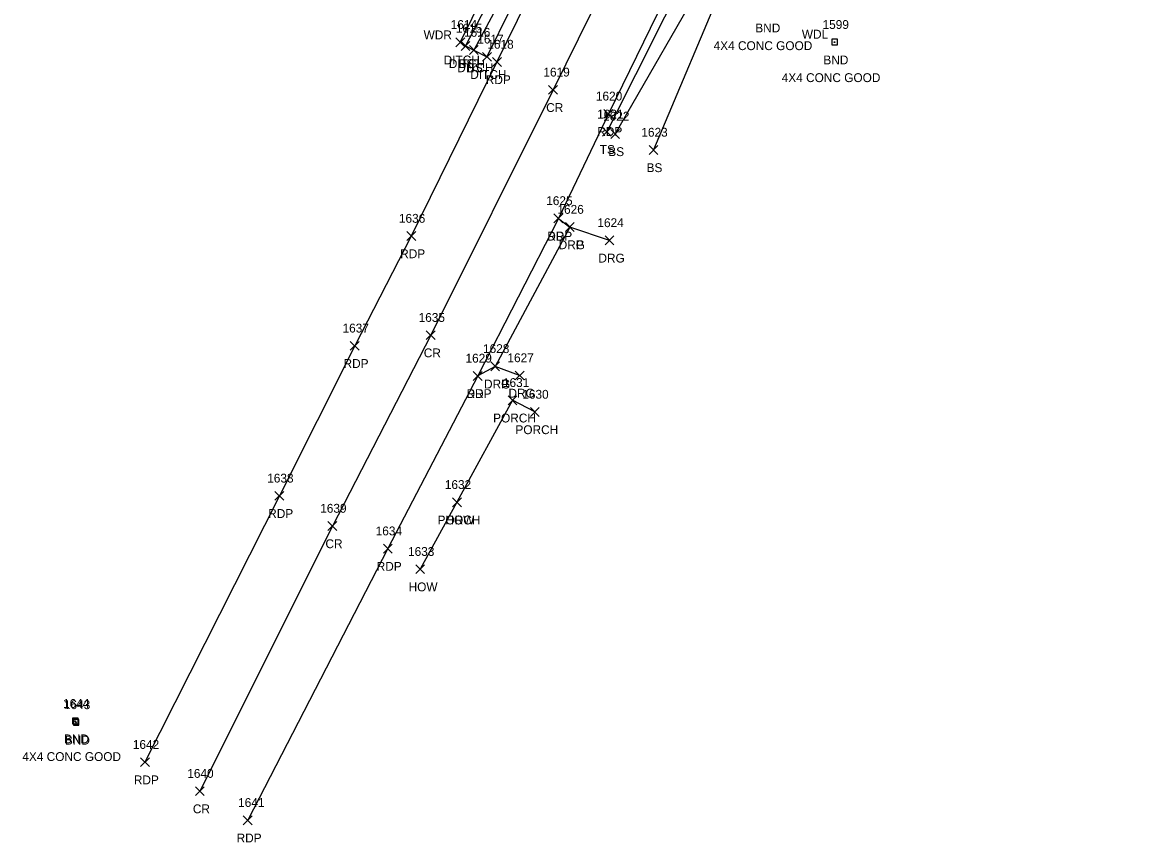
# Model space of a CAD drawing. Extents: x 1551995 to 1555700, y 777276 to 783130.
# Drawn here: x 1554635 to 1554889.9, y 777276.2 to 777461.3 of the extents above; entities that cross this region are included whole.
import ezdxf

# ---------------------------------------------------------------- set-up
doc = ezdxf.new("R2010")
doc.units = 0
for name, color, linetype in [('D_A', 7, 'Continuous'), ('D_I', 7, 'Continuous'), ('D_TIC', 7, 'Continuous'), ('DD', 7, 'Continuous'), ('L_A', 7, 'Continuous'), ('L_I', 7, 'Continuous'), ('L_TIC', 7, 'Continuous'), ('LBC', 7, 'Continuous'), ('LBF', 7, 'Continuous'), ('LELB', 7, 'Continuous'), ('Level 18', 7, 'Continuous'), ('M_A', 7, 'Continuous'), ('M_C', 7, 'Continuous'), ('M_I', 7, 'Continuous'), ('P_A', 7, 'Continuous'), ('P_I', 7, 'Continuous'), ('P_TIC', 7, 'Continuous'), ('PET', 7, 'Continuous'), ('PRC', 7, 'Continuous'), ('R_A', 7, 'Continuous'), ('R_I', 7, 'Continuous'), ('R_TIC', 7, 'Continuous'), ('RDG', 7, 'Continuous'), ('RDP', 7, 'Continuous')]:
    doc.layers.add(name, color=color, linetype=linetype)

msp = doc.modelspace()

# ---------------------------------------------------------------- linework, layer by layer
at = {"layer": 'D_TIC'}
for points in [[(1554732.83, 777455.87), (1554734.83, 777457.87)], [(1554734.83, 777455.87), (1554732.83, 777457.87)], [(1554734, 777455.04), (1554736, 777457.04)], [(1554736, 777455.04), (1554734, 777457.04)], [(1554735.9, 777454.11), (1554737.9, 777456.11)], [(1554737.9, 777454.11), (1554735.9, 777456.11)], [(1554738.85, 777452.59), (1554740.85, 777454.59)], [(1554740.85, 777452.59), (1554738.85, 777454.59)], [(1554738.85, 777452.59), (1554740.85, 777454.59)], [(1554740.85, 777452.59), (1554738.85, 777454.59)]]:
    msp.add_lwpolyline(points, dxfattribs=at)
at = {"layer": 'DD'}
for points in [[(1554853.39, 777826.98), (1554841.81, 777777.5), (1554835.76, 777743.69), (1554828.13, 777697.14), (1554822.33, 777678.76), (1554820.5, 777673.08), (1554821.28, 777667.69), (1554820.54, 777665.87), (1554819.99, 777658.61), (1554821.52, 777659.17), (1554812.27, 777628.19), (1554798.58, 777600.46), (1554777.91, 777552.75), (1554765.73, 777525.09), (1554749.72, 777489.17), (1554733.83, 777456.87), (1554735, 777456.04), (1554736.9, 777455.11), (1554739.85, 777453.59)], [(1554815.91, 777627.5), (1554804.43, 777598.27), (1554784.48, 777549.49), (1554771.86, 777522.02), (1554755.84, 777486.17), (1554739.85, 777453.59)]]:
    msp.add_lwpolyline(points, dxfattribs=at)
at = {"layer": 'L_TIC'}
for points in [[(1554734, 777455.04), (1554736, 777457.04)], [(1554736, 777455.04), (1554734, 777457.04)], [(1554735.9, 777454.11), (1554737.9, 777456.11)], [(1554737.9, 777454.11), (1554735.9, 777456.11)], [(1554765.91, 777435.65), (1554767.91, 777437.65)], [(1554767.91, 777435.65), (1554765.91, 777437.65)], [(1554767.81, 777435.17), (1554769.81, 777437.17)], [(1554769.81, 777435.17), (1554767.81, 777437.17)], [(1554776.45, 777431.55), (1554778.45, 777433.55)], [(1554778.45, 777431.55), (1554776.45, 777433.55)], [(1554744.63, 777375.02), (1554746.63, 777377.02)], [(1554746.63, 777375.02), (1554744.63, 777377.02)], [(1554749.65, 777372.38), (1554751.65, 777374.38)], [(1554751.65, 777372.38), (1554749.65, 777374.38)], [(1554732.08, 777351.99), (1554734.08, 777353.99)], [(1554734.08, 777351.99), (1554732.08, 777353.99)], [(1554732.08, 777351.99), (1554734.08, 777353.99)], [(1554734.08, 777351.99), (1554732.08, 777353.99)], [(1554723.77, 777336.88), (1554725.77, 777338.88)], [(1554725.77, 777336.88), (1554723.77, 777338.88)]]:
    msp.add_lwpolyline(points, dxfattribs=at)
at = {"layer": 'LBC'}
msp.add_lwpolyline([(1554733.08, 777352.99), (1554724.77, 777337.88)], dxfattribs=at)
at = {"layer": 'LBF'}
msp.add_lwpolyline([(1554750.65, 777373.38), (1554745.63, 777376.02), (1554733.08, 777352.99)], dxfattribs=at)
at = {"layer": 'LELB'}
for points in [[(1554855.73, 777827.33), (1554843.83, 777776.52), (1554838.11, 777743.68), (1554829.99, 777696.83), (1554823.99, 777679.3), (1554821.48, 777673.86), (1554821.86, 777673.52), (1554823.73, 777663.64), (1554822.4, 777659.03), (1554813.94, 777627.98), (1554800.18, 777599.92), (1554780.06, 777551.51), (1554767.45, 777524.55), (1554751.73, 777488.16), (1554735, 777456.04)], [(1554857.76, 777827.38), (1554846.36, 777775.83), (1554840.77, 777743.18), (1554831.41, 777696.67), (1554825.48, 777677.69), (1554824.51, 777673.63), (1554823.78, 777673.32), (1554824.92, 777663.42), (1554823.59, 777658.72), (1554814.97, 777627.54), (1554801.99, 777599.47), (1554782.65, 777550.32), (1554769.22, 777523.47), (1554754.18, 777487.46), (1554736.9, 777455.11)], [(1554865.05, 777604.93), (1554861.66, 777583.06), (1554845.3, 777549.29), (1554838.79, 777524.5), (1554825.26, 777531.03), (1554821.87, 777528.28), (1554813.37, 777517.61), (1554805.18, 777504.08), (1554790.4, 777473.73), (1554768.81, 777436.17)], [(1554824.88, 777531.45), (1554822.62, 777533.94), (1554819.85, 777529.46), (1554812.02, 777518.71), (1554803.48, 777505.5), (1554786.44, 777475.49), (1554766.91, 777436.65)], [(1554824.11, 777527.47), (1554814.83, 777516.49), (1554807.91, 777502.52), (1554794.11, 777472.13), (1554777.45, 777432.55)]]:
    msp.add_lwpolyline(points, dxfattribs=at)
at = {"layer": 'Level 18'}
for p, q in [((1554818.99, 777457.54), (1554817.74, 777457.54)), ((1554817.74, 777457.54), (1554817.74, 777456.29)), ((1554818.99, 777457.54), (1554817.74, 777457.54)), ((1554817.74, 777457.54), (1554817.74, 777456.29)), ((1554818.99, 777456.29), (1554818.99, 777457.54)), ((1554818.99, 777456.29), (1554818.99, 777457.54)), ((1554817.74, 777456.29), (1554818.99, 777456.29)), ((1554817.74, 777456.29), (1554818.99, 777456.29)), ((1554647.51, 777304.22), (1554646.26, 777304.22)), ((1554646.26, 777304.22), (1554646.26, 777302.97)), ((1554647.51, 777304.22), (1554646.26, 777304.22)), ((1554646.26, 777304.22), (1554646.26, 777302.97)), ((1554647.71, 777303.93), (1554646.46, 777303.93)), ((1554646.46, 777303.93), (1554646.46, 777302.68)), ((1554647.71, 777303.93), (1554646.46, 777303.93)), ((1554646.46, 777303.93), (1554646.46, 777302.68)), ((1554647.51, 777302.97), (1554647.51, 777304.22)), ((1554647.51, 777302.97), (1554647.51, 777304.22)), ((1554647.71, 777302.68), (1554647.71, 777303.93)), ((1554647.71, 777302.68), (1554647.71, 777303.93)), ((1554646.26, 777302.97), (1554647.51, 777302.97)), ((1554646.26, 777302.97), (1554647.51, 777302.97)), ((1554646.46, 777302.68), (1554647.71, 777302.68)), ((1554646.46, 777302.68), (1554647.71, 777302.68))]:
    msp.add_line(p, q, dxfattribs=at)
for centre in [(1554818.34, 777456.88), (1554646.86, 777303.56), (1554647.06, 777303.27)]:
    msp.add_circle(centre, 0.0833, dxfattribs=at)
at = {"layer": 'P_TIC'}
for points in [[(1554741.1, 777451.42), (1554743.1, 777453.42)], [(1554743.1, 777451.42), (1554741.1, 777453.42)], [(1554753.78, 777445.13), (1554755.78, 777447.13)], [(1554755.78, 777445.13), (1554753.78, 777447.13)], [(1554766.28, 777439.72), (1554768.28, 777441.72)], [(1554768.28, 777439.72), (1554766.28, 777441.72)], [(1554754.97, 777416.1), (1554756.97, 777418.1)], [(1554756.97, 777416.1), (1554754.97, 777418.1)], [(1554721.77, 777412.11), (1554723.77, 777414.11)], [(1554723.77, 777412.11), (1554721.77, 777414.11)], [(1554726.16, 777389.73), (1554728.16, 777391.73)], [(1554728.16, 777389.73), (1554726.16, 777391.73)], [(1554708.98, 777387.33), (1554710.98, 777389.33)], [(1554710.98, 777387.33), (1554708.98, 777389.33)], [(1554736.76, 777380.53), (1554738.76, 777382.53)], [(1554738.76, 777380.53), (1554736.76, 777382.53)], [(1554691.97, 777353.45), (1554693.97, 777355.45)], [(1554693.97, 777353.45), (1554691.97, 777355.45)], [(1554703.95, 777346.63), (1554705.95, 777348.63)], [(1554705.95, 777346.63), (1554703.95, 777348.63)], [(1554716.46, 777341.52), (1554718.46, 777343.52)], [(1554718.46, 777341.52), (1554716.46, 777343.52)], [(1554661.63, 777293.3), (1554663.63, 777295.3)], [(1554663.63, 777293.3), (1554661.63, 777295.3)], [(1554674, 777286.76), (1554676, 777288.76)], [(1554676, 777286.76), (1554674, 777288.76)], [(1554684.83, 777280.18), (1554686.83, 777282.18)], [(1554686.83, 777280.18), (1554684.83, 777282.18)]]:
    msp.add_lwpolyline(points, dxfattribs=at)
at = {"layer": 'PET'}
for points in [[(1554862.74, 777826.66), (1554851.19, 777774.32), (1554844.64, 777742.45), (1554834.58, 777696.01), (1554825.9, 777662.94), (1554824.47, 777658.25), (1554815.91, 777627.5), (1554805.87, 777597.98), (1554786.84, 777548.46), (1554774.55, 777520.74), (1554758.12, 777485.1), (1554742.1, 777452.42), (1554722.77, 777413.11), (1554709.98, 777388.33), (1554692.97, 777354.45), (1554662.63, 777294.3)], [(1554889.9, 777822.39), (1554877.4, 777767.74), (1554869.61, 777731.46), (1554860.02, 777689.61), (1554848.79, 777645.37), (1554834.77, 777600.99), (1554821.88, 777564.77), (1554812, 777537.71), (1554799.6, 777509.17), (1554784.62, 777476.27), (1554767.28, 777440.72), (1554755.97, 777417.1), (1554737.76, 777381.53), (1554717.46, 777342.52), (1554685.83, 777281.18)]]:
    msp.add_lwpolyline(points, dxfattribs=at)
at = {"layer": 'PRC'}
msp.add_lwpolyline([(1554876.72, 777824.26), (1554864.6, 777770.35), (1554858.03, 777739.92), (1554847.21, 777693.38), (1554836.59, 777653.01), (1554828.61, 777623.61), (1554818.04, 777593.07), (1554799.63, 777543.85), (1554787.19, 777515.25), (1554771.79, 777480.71), (1554754.78, 777446.13), (1554727.16, 777390.73), (1554704.95, 777347.63), (1554675, 777287.76)], dxfattribs=at)
at = {"layer": 'R_TIC'}
for points in [[(1554754.97, 777416.1), (1554756.97, 777418.1)], [(1554756.97, 777416.1), (1554754.97, 777418.1)], [(1554757.57, 777414.14), (1554759.57, 777416.14)], [(1554759.57, 777414.14), (1554757.57, 777416.14)], [(1554757.57, 777414.14), (1554759.57, 777416.14)], [(1554759.57, 777414.14), (1554757.57, 777416.14)], [(1554766.53, 777411.13), (1554768.53, 777413.13)], [(1554768.53, 777411.13), (1554766.53, 777413.13)], [(1554740.7, 777382.69), (1554742.7, 777384.69)], [(1554742.7, 777382.69), (1554740.7, 777384.69)], [(1554740.7, 777382.69), (1554742.7, 777384.69)], [(1554742.7, 777382.69), (1554740.7, 777384.69)], [(1554746.22, 777380.63), (1554748.22, 777382.63)], [(1554748.22, 777380.63), (1554746.22, 777382.63)], [(1554736.76, 777380.53), (1554738.76, 777382.53)], [(1554738.76, 777380.53), (1554736.76, 777382.53)]]:
    msp.add_lwpolyline(points, dxfattribs=at)
at = {"layer": 'RDG'}
for points in [[(1554767.53, 777412.13), (1554758.57, 777415.14)], [(1554747.22, 777381.63), (1554741.7, 777383.69)]]:
    msp.add_lwpolyline(points, dxfattribs=at)
at = {"layer": 'RDP'}
msp.add_lwpolyline([(1554755.97, 777417.1), (1554758.57, 777415.14), (1554741.7, 777383.69), (1554737.76, 777381.53)], dxfattribs=at)

# ---------------------------------------------------------------- texts
at = {"layer": 'D_A'}
for p in [(1554730.07, 777451.87), (1554731.24, 777451.04), (1554733.14, 777450.11), (1554736.08, 777448.59), (1554736.08, 777448.59)]:
    msp.add_text('DITCH', height=2, dxfattribs=at).set_placement(p)
at = {"layer": 'D_I'}
for s, p in [('1614', (1554731.66, 777459.87)), ('1615', (1554732.83, 777459.04)), ('1616', (1554734.67, 777458.11)), ('1617', (1554737.67, 777456.59)), ('1617', (1554737.67, 777456.59))]:
    msp.add_text(s, height=2, dxfattribs=at).set_placement(p)
at = {"layer": 'L_A'}
for s, p in [('WDR', (1554725.55, 777457.54)), ('WDL', (1554810.96, 777457.7)), ('BS', (1554733.44, 777451.04)), ('BS', (1554735.34, 777450.11)), ('TS', (1554765.32, 777431.65)), ('BS', (1554767.25, 777431.17)), ('BS', (1554775.89, 777427.55)), ('PORCH', (1554741.25, 777371.02)), ('PORCH', (1554746.28, 777368.38)), ('PORCH', (1554728.7, 777347.99)), ('HOW', (1554730.47, 777347.99)), ('HOW', (1554722.16, 777332.88))]:
    msp.add_text(s, height=2, dxfattribs=at).set_placement(p)
at = {"layer": 'L_I'}
for s, p in [('1615', (1554732.83, 777459.04)), ('1616', (1554734.67, 777458.11)), ('1621', (1554764.74, 777439.65)), ('1622', (1554766.07, 777439.17)), ('1623', (1554774.71, 777435.55)), ('1631', (1554743.46, 777379.02)), ('1630', (1554747.83, 777376.38)), ('1632', (1554730.34, 777355.99)), ('1632', (1554730.34, 777355.99)), ('1633', (1554722.03, 777340.88))]:
    msp.add_text(s, height=2, dxfattribs=at).set_placement(p)
at = {"layer": 'M_A'}
for p in [(1554800.45, 777459.1), (1554815.82, 777451.88), (1554644.34, 777298.56), (1554644.55, 777298.28)]:
    msp.add_text('BND', height=2, dxfattribs=at).set_placement(p)
at = {"layer": 'M_C'}
for p in [(1554791.03, 777455.1), (1554806.41, 777447.88), (1554634.93, 777294.56)]:
    msp.add_text('4X4 CONC GOOD', height=2, dxfattribs=at).set_placement(p)
at = {"layer": 'M_I'}
for s, p in [('1599', (1554815.64, 777459.88)), ('1644', (1554644.12, 777306.56)), ('1643', (1554644.32, 777306.28))]:
    msp.add_text(s, height=2, dxfattribs=at).set_placement(p)
at = {"layer": 'P_A'}
for s, p in [('RDP', (1554739.59, 777447.42)), ('CR', (1554753.22, 777441.13)), ('RDP', (1554764.77, 777435.72)), ('RDP', (1554753.46, 777412.1)), ('RDP', (1554720.26, 777408.11)), ('CR', (1554725.59, 777385.73)), ('RDP', (1554707.47, 777383.33)), ('RDP', (1554735.24, 777376.53)), ('RDP', (1554690.46, 777349.45)), ('CR', (1554703.38, 777342.63)), ('RDP', (1554714.95, 777337.52)), ('RDP', (1554660.12, 777289.3)), ('CR', (1554673.44, 777282.76)), ('RDP', (1554683.32, 777276.18))]:
    msp.add_text(s, height=2, dxfattribs=at).set_placement(p)
at = {"layer": 'P_I'}
for s, p in [('1618', (1554739.93, 777455.42)), ('1619', (1554752.6, 777449.13)), ('1620', (1554764.45, 777443.72)), ('1625', (1554753.23, 777420.1)), ('1636', (1554719.97, 777416.11)), ('1635', (1554724.42, 777393.73)), ('1637', (1554707.24, 777391.33)), ('1629', (1554735.01, 777384.53)), ('1638', (1554690.23, 777357.45)), ('1639', (1554702.2, 777350.63)), ('1634', (1554714.72, 777345.52)), ('1642', (1554659.89, 777297.3)), ('1640', (1554672.18, 777290.76)), ('1641', (1554683.66, 777284.18))]:
    msp.add_text(s, height=2, dxfattribs=at).set_placement(p)
at = {"layer": 'R_A'}
for s, p in [('DRP', (1554753.46, 777412.1)), ('DRG', (1554756.05, 777410.14)), ('DRP', (1554756.05, 777410.14)), ('DRG', (1554765.02, 777407.13)), ('DRG', (1554739.19, 777378.69)), ('DRP', (1554739.19, 777378.69)), ('DRP', (1554735.24, 777376.53)), ('DRG', (1554744.71, 777376.63))]:
    msp.add_text(s, height=2, dxfattribs=at).set_placement(p)
at = {"layer": 'R_I'}
for s, p in [('1625', (1554753.23, 777420.1)), ('1626', (1554755.77, 777418.14)), ('1626', (1554755.77, 777418.14)), ('1624', (1554764.79, 777415.13)), ('1628', (1554738.96, 777386.69)), ('1628', (1554738.96, 777386.69)), ('1629', (1554735.01, 777384.53)), ('1627', (1554744.48, 777384.63))]:
    msp.add_text(s, height=2, dxfattribs=at).set_placement(p)

doc.saveas('drawing.dxf')
